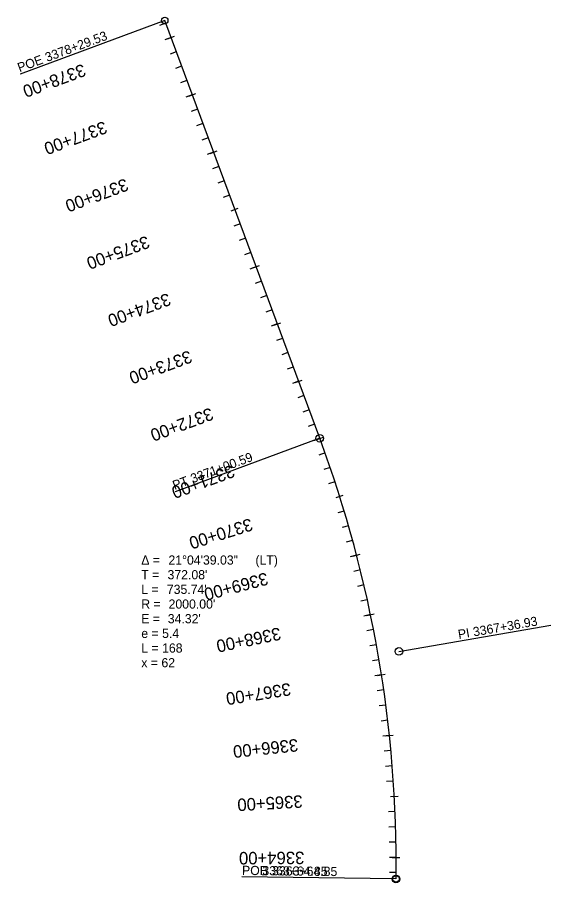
# Model space of a CAD drawing. Extents: x 20505960 to 20506832, y 7969161 to 7970577.
import ezdxf

# ---------------------------------------------------------------- set-up
doc = ezdxf.new("R2010")
doc.units = 0
for name, color, linetype in [('Alignment', 7, 'Continuous'), ('TextAlignment', 7, 'Continuous'), ('TextAlignmentLrg', 7, 'Continuous'), ('TextAlignmentSml', 7, 'Continuous')]:
    doc.layers.add(name, color=color, linetype=linetype)

msp = doc.modelspace()

# ---------------------------------------------------------------- linework, layer by layer
at = {"layer": 'Alignment'}
msp.add_line((20506454.4, 7969888.3), (20506200.8, 7970571.7), dxfattribs=at)
msp.add_arc((20504579.3, 7969192.6), 2000, 359.2791, 20.3566, dxfattribs=at)
at = {"layer": 'TextAlignment'}
for p, q in [((20506200.8, 7970571.7), (20505964.5, 7970484.1)), ((20505964.5, 7970484.1), (20505964.5, 7970484.1)), ((20506454.4, 7969888.3), (20506218.1, 7969800.6)), ((20506218.1, 7969800.6), (20506218.1, 7969800.6)), ((20506583.8, 7969539.5), (20506832.1, 7969582.4)), ((20506832.1, 7969582.4), (20506832.1, 7969582.4)), ((20506579.1, 7969167.4), (20506327.1, 7969170.6)), ((20506327.1, 7969170.6), (20506327.1, 7969170.6)), ((20506579.1, 7969167.4), (20506327.1, 7969170.6)), ((20506327.1, 7969170.6), (20506327.1, 7969170.6))]:
    msp.add_line(p, q, dxfattribs=at)
for centre, radius in [((20506200.8, 7970571.7), 5.34), ((20506454.4, 7969888.3), 6.24), ((20506583.8, 7969539.5), 6.24), ((20506579.1, 7969167.4), 6.24), ((20506579.1, 7969167.4), 5.34)]:
    msp.add_circle(centre, radius, dxfattribs=at)
at = {"layer": 'TextAlignmentLrg'}
for p, q in [((20506211.1, 7970544), (20506200.8, 7970540.2)), ((20506245.9, 7970450.3), (20506235.6, 7970446.5)), ((20506280.6, 7970356.5), (20506270.4, 7970352.7)), ((20506309.7, 7970260.6), (20506321.2, 7970264.9)), ((20506350.2, 7970169), (20506340, 7970165.2)), ((20506385, 7970075.3), (20506374.8, 7970071.5)), ((20506419.8, 7969981.5), (20506409.6, 7969977.7)), ((20506454.6, 7969887.7), (20506444.3, 7969884)), ((20506481.1, 7969791.3), (20506492.8, 7969795)), ((20506514.6, 7969697.1), (20506504, 7969694.3)), ((20506537.4, 7969599.7), (20506526.7, 7969597.5)), ((20506555.3, 7969501.3), (20506544.5, 7969499.6)), ((20506568.3, 7969402.2), (20506557.4, 7969401)), ((20506570.1, 7969302.2), (20506582.4, 7969302.8)), ((20506579.3, 7969202.6), (20506568.3, 7969202.5))]:
    msp.add_line(p, q, dxfattribs=at)
at = {"layer": 'TextAlignmentSml'}
for p, q in [((20506202.4, 7970567.5), (20506192.1, 7970563.7)), ((20506205.3, 7970541.9), (20506216.8, 7970546.2)), ((20506219.8, 7970520.6), (20506209.5, 7970516.8)), ((20506228.5, 7970497.2), (20506218.2, 7970493.4)), ((20506237.2, 7970473.7), (20506226.9, 7970469.9)), ((20506240.1, 7970448.1), (20506251.6, 7970452.4)), ((20506254.6, 7970426.8), (20506244.3, 7970423)), ((20506263.3, 7970403.4), (20506253, 7970399.6)), ((20506272, 7970380), (20506261.7, 7970376.2)), ((20506274.9, 7970354.4), (20506286.4, 7970358.6)), ((20506289.3, 7970333.1), (20506279.1, 7970329.3)), ((20506298, 7970309.6), (20506287.8, 7970305.8)), ((20506306.7, 7970286.2), (20506296.5, 7970282.4)), ((20506309.7, 7970260.6), (20506321.2, 7970264.9)), ((20506324.1, 7970239.3), (20506313.9, 7970235.5)), ((20506332.8, 7970215.9), (20506322.6, 7970212.1)), ((20506341.5, 7970192.4), (20506331.3, 7970188.6)), ((20506344.5, 7970166.9), (20506356, 7970171.1)), ((20506358.9, 7970145.6), (20506348.7, 7970141.8)), ((20506367.6, 7970122.1), (20506357.4, 7970118.3)), ((20506376.3, 7970098.7), (20506366.1, 7970094.9)), ((20506379.3, 7970073.1), (20506390.7, 7970077.4)), ((20506393.7, 7970051.8), (20506383.5, 7970048)), ((20506402.4, 7970028.4), (20506392.2, 7970024.6)), ((20506411.1, 7970004.9), (20506400.9, 7970001.1)), ((20506414.1, 7969979.4), (20506425.5, 7969983.6)), ((20506428.5, 7969958.1), (20506418.3, 7969954.3)), ((20506437.2, 7969934.6), (20506426.9, 7969930.8)), ((20506445.9, 7969911.2), (20506435.6, 7969907.4)), ((20506448.8, 7969885.6), (20506460.3, 7969889.9)), ((20506463.1, 7969864.3), (20506452.8, 7969860.6)), ((20506471.4, 7969840.7), (20506461, 7969837.1)), ((20506479.3, 7969816.9), (20506468.9, 7969813.5)), ((20506481.1, 7969791.3), (20506492.8, 7969795)), ((20506494.3, 7969769.3), (20506483.9, 7969766.1)), ((20506501.4, 7969745.3), (20506490.9, 7969742.3)), ((20506508.2, 7969721.2), (20506497.6, 7969718.3)), ((20506508.7, 7969695.5), (20506520.5, 7969698.6)), ((20506520.8, 7969672.8), (20506510.2, 7969670.2)), ((20506526.6, 7969648.5), (20506516, 7969646)), ((20506532.2, 7969624.1), (20506521.5, 7969621.8)), ((20506531.4, 7969598.5), (20506543.4, 7969600.9)), ((20506542.3, 7969575.2), (20506531.6, 7969573.1)), ((20506547, 7969550.6), (20506536.2, 7969548.7)), ((20506551.3, 7969526), (20506540.5, 7969524.2)), ((20506549.3, 7969500.4), (20506561.4, 7969502.3)), ((20506559, 7969476.6), (20506548.2, 7969475)), ((20506562.4, 7969451.8), (20506551.6, 7969450.4)), ((20506565.5, 7969427), (20506554.6, 7969425.7)), ((20506562.2, 7969401.5), (20506574.4, 7969402.8)), ((20506570.7, 7969377.3), (20506559.9, 7969376.3)), ((20506572.9, 7969352.4), (20506562, 7969351.5)), ((20506574.7, 7969327.5), (20506563.8, 7969326.7)), ((20506570.1, 7969302.2), (20506582.4, 7969302.8)), ((20506577.5, 7969277.5), (20506566.6, 7969277.1)), ((20506578.4, 7969252.6), (20506567.5, 7969252.2)), ((20506579, 7969227.6), (20506568.1, 7969227.4)), ((20506573.1, 7969202.5), (20506585.4, 7969202.6)), ((20506579.2, 7969177.6), (20506568.3, 7969177.6))]:
    msp.add_line(p, q, dxfattribs=at)

# ---------------------------------------------------------------- texts
at = {"layer": 'TextAlignment'}
for s, rotation, p in [('3378+29.53', 20.3566, (20506008.5, 7970503.9)), ('POE ', 20.3566, (20505963.4, 7970487.1)), ('3371+00.59', 20.3566, (20506246.5, 7969814.7)), ('PT', 20.3566, (20506217, 7969803.7)), ('3367+36.93', 9.8178, (20506706.5, 7969564)), ('PI ', 9.8178, (20506681.9, 7969559.8)), ('PC', 359.2791, (20506327.2, 7969173.9)), ('POB ', 359.2791, (20506327.2, 7969173.9)), ('3363+64.85', 359.2791, (20506360.5, 7969173.5)), ('3363+64.85', 359.2791, (20506376.5, 7969173.3))]:
    msp.add_text(s, height=15, rotation=rotation, dxfattribs=at).set_placement(p)
for s, p in [('Δ = ', (20506162.5, 7969681.6)), ('21°04\'39.03"', (20506206.9, 7969681.6)), (' (LT)', (20506343.6, 7969681.6)), ('T = ', (20506162.5, 7969657.6)), ("372.08'", (20506205.4, 7969657.6)), ('L = ', (20506162.5, 7969633.6)), ("735.74'", (20506204.3, 7969633.6)), ('R = ', (20506162.5, 7969609.6)), ("2000.00'", (20506207.1, 7969609.6)), ('E = ', (20506162.5, 7969585.6)), ("34.32'", (20506205.8, 7969585.6)), ('e = 5.4', (20506162.5, 7969561.6)), ('L = 168', (20506162.5, 7969537.6)), ('x = 62', (20506162.5, 7969513.6))]:
    msp.add_text(s, height=15, dxfattribs=at).set_placement(p)
at = {"layer": 'TextAlignmentLrg'}
for s, rotation, p in [('3375+00', 200.3566, (20506171.3, 7970220.1)), ('3370+00', 197.4748, (20506340.8, 7969757.8)), ('3365+00', 183.1508, (20506425.9, 7969304.4))]:
    msp.add_text(s, height=20.4, rotation=rotation, dxfattribs=at).set_placement(p)
at = {"layer": 'TextAlignmentSml'}
for s, rotation, p in [('3378+00', 200.3566, (20506066.9, 7970501.4)), ('3377+00', 200.3566, (20506101.7, 7970407.7)), ('3376+00', 200.3566, (20506136.5, 7970313.9)), ('3375+00', 200.3566, (20506171.3, 7970220.1)), ('3374+00', 200.3566, (20506206, 7970126.4)), ('3373+00', 200.3566, (20506240.8, 7970032.6)), ('3372+00', 200.3566, (20506275.6, 7969938.9)), ('3371+00', 200.3396, (20506310.4, 7969845.2)), ('3370+00', 197.4748, (20506340.8, 7969757.8)), ('3369+00', 194.61, (20506366.9, 7969669.1)), ('3368+00', 191.7452, (20506388.5, 7969579.2)), ('3367+00', 188.8804, (20506405.5, 7969488.2)), ('3366+00', 186.0156, (20506418, 7969396.6)), ('3365+00', 183.1508, (20506425.9, 7969304.4)), ('3364+00', 180.286, (20506429.2, 7969212))]:
    msp.add_text(s, height=20.4, rotation=rotation, dxfattribs=at).set_placement(p)

doc.saveas('drawing.dxf')
